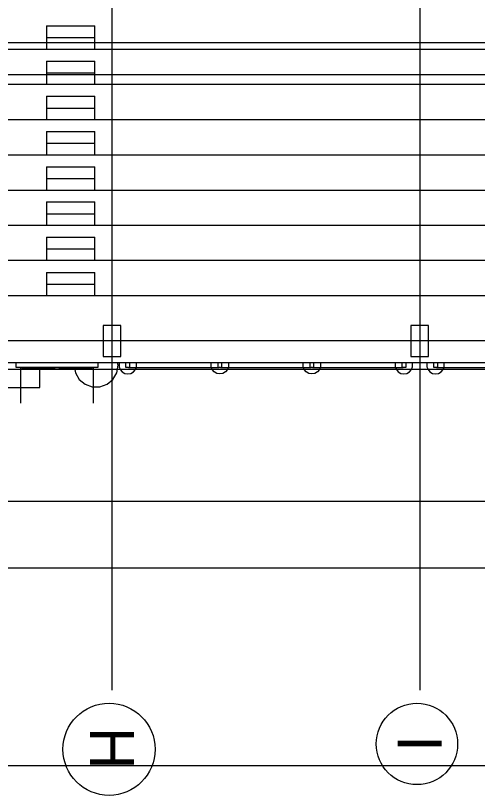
# Model space of a CAD drawing. Extents: x -264165 to -263575, y -1242333 to -1242036.
# Drawn here: x -263871.66 to -263861.16, y -1242251.13 to -1242233.41 of the extents above; entities that cross this region are included whole.
import ezdxf

# ---------------------------------------------------------------- set-up
doc = ezdxf.new("R2010")
doc.units = 0
doc.layers.add('KFA_HESCON_OSI_STAVBY', color=7, linetype='Continuous')
doc.layers.add('KFA_SITUACIA_DRS_VYTYCOVAK_SEDA', color=7, linetype='Continuous')

msp = doc.modelspace()

# ---------------------------------------------------------------- linework, layer by layer
at = {"layer": 'KFA_HESCON_OSI_STAVBY'}
for p, q in [((-263869.468, -1242080.447), (-263869.468, -1242248.737)), ((-263862.468, -1242080.447), (-263862.468, -1242248.737)), ((-263787.486, -1242234.032), (-263921.823, -1242234.032)), ((-263787.486, -1242240.807), (-263921.823, -1242240.807))]:
    msp.add_line(p, q, dxfattribs=at)
for centre, radius in [((-263869.533, -1242250.084), 1.047), ((-263862.533, -1242249.962), 0.925)]:
    msp.add_circle(centre, radius, dxfattribs=at)
at = {"layer": 'KFA_SITUACIA_DRS_VYTYCOVAK_SEDA'}
for p, q in [((-263870.956, -1242233.649), (-263870.956, -1242233.916)), ((-263870.956, -1242233.649), (-263870.956, -1242233.916)), ((-263870.956, -1242233.649), (-263869.856, -1242233.649)), ((-263870.956, -1242233.649), (-263869.856, -1242233.649)), ((-263869.856, -1242233.916), (-263869.856, -1242233.649)), ((-263869.856, -1242233.916), (-263869.856, -1242233.649)), ((-263870.956, -1242233.916), (-263869.856, -1242233.916)), ((-263870.956, -1242233.916), (-263869.856, -1242233.916)), ((-263870.956, -1242233.916), (-263870.956, -1242234.182)), ((-263870.956, -1242233.916), (-263870.956, -1242234.182)), ((-263869.856, -1242234.182), (-263869.856, -1242233.916)), ((-263869.856, -1242234.182), (-263869.856, -1242233.916)), ((-263869.468, -1242234.182), (-263876.468, -1242234.182)), ((-263869.468, -1242234.182), (-263876.468, -1242234.182)), ((-263862.468, -1242234.182), (-263869.468, -1242234.182)), ((-263862.468, -1242234.182), (-263869.468, -1242234.182)), ((-263855.468, -1242234.182), (-263862.468, -1242234.182)), ((-263855.468, -1242234.182), (-263862.468, -1242234.182)), ((-263870.956, -1242234.449), (-263870.956, -1242234.716)), ((-263870.956, -1242234.449), (-263870.956, -1242234.716)), ((-263870.956, -1242234.449), (-263869.856, -1242234.449)), ((-263870.956, -1242234.449), (-263869.856, -1242234.449)), ((-263869.856, -1242234.716), (-263869.856, -1242234.449)), ((-263869.856, -1242234.716), (-263869.856, -1242234.449)), ((-263812.068, -1242234.757), (-263891.868, -1242234.757)), ((-263870.956, -1242234.716), (-263869.856, -1242234.716)), ((-263870.956, -1242234.716), (-263869.856, -1242234.716)), ((-263870.956, -1242234.716), (-263870.956, -1242234.982)), ((-263870.956, -1242234.716), (-263870.956, -1242234.982)), ((-263869.856, -1242234.982), (-263869.856, -1242234.716)), ((-263869.856, -1242234.982), (-263869.856, -1242234.716)), ((-263869.468, -1242234.982), (-263876.468, -1242234.982)), ((-263869.468, -1242234.982), (-263876.468, -1242234.982)), ((-263862.468, -1242234.982), (-263869.468, -1242234.982)), ((-263862.468, -1242234.982), (-263869.468, -1242234.982)), ((-263855.468, -1242234.982), (-263862.468, -1242234.982)), ((-263855.468, -1242234.982), (-263862.468, -1242234.982)), ((-263870.956, -1242235.249), (-263870.956, -1242235.516)), ((-263870.956, -1242235.249), (-263870.956, -1242235.516)), ((-263870.956, -1242235.249), (-263869.856, -1242235.249)), ((-263870.956, -1242235.249), (-263869.856, -1242235.249)), ((-263869.856, -1242235.516), (-263869.856, -1242235.249)), ((-263869.856, -1242235.516), (-263869.856, -1242235.249)), ((-263870.956, -1242235.516), (-263869.856, -1242235.516)), ((-263870.956, -1242235.516), (-263869.856, -1242235.516)), ((-263870.956, -1242235.516), (-263870.956, -1242235.782)), ((-263870.956, -1242235.516), (-263870.956, -1242235.782)), ((-263869.856, -1242235.782), (-263869.856, -1242235.516)), ((-263869.856, -1242235.782), (-263869.856, -1242235.516)), ((-263869.468, -1242235.782), (-263876.468, -1242235.782)), ((-263869.468, -1242235.782), (-263876.468, -1242235.782)), ((-263862.468, -1242235.782), (-263869.468, -1242235.782)), ((-263862.468, -1242235.782), (-263869.468, -1242235.782)), ((-263855.468, -1242235.782), (-263862.468, -1242235.782)), ((-263855.468, -1242235.782), (-263862.468, -1242235.782)), ((-263870.956, -1242236.049), (-263870.956, -1242236.316)), ((-263870.956, -1242236.049), (-263870.956, -1242236.316)), ((-263870.956, -1242236.049), (-263869.856, -1242236.049)), ((-263870.956, -1242236.049), (-263869.856, -1242236.049)), ((-263869.856, -1242236.316), (-263869.856, -1242236.049)), ((-263869.856, -1242236.316), (-263869.856, -1242236.049)), ((-263870.956, -1242236.316), (-263869.856, -1242236.316)), ((-263870.956, -1242236.316), (-263869.856, -1242236.316)), ((-263870.956, -1242236.316), (-263870.956, -1242236.582)), ((-263870.956, -1242236.316), (-263870.956, -1242236.582)), ((-263869.856, -1242236.582), (-263869.856, -1242236.316)), ((-263869.856, -1242236.582), (-263869.856, -1242236.316)), ((-263869.468, -1242236.582), (-263876.468, -1242236.582)), ((-263869.468, -1242236.582), (-263876.468, -1242236.582)), ((-263862.468, -1242236.582), (-263869.468, -1242236.582)), ((-263862.468, -1242236.582), (-263869.468, -1242236.582)), ((-263855.468, -1242236.582), (-263862.468, -1242236.582)), ((-263855.468, -1242236.582), (-263862.468, -1242236.582)), ((-263870.956, -1242236.849), (-263870.956, -1242237.116)), ((-263870.956, -1242236.849), (-263870.956, -1242237.116)), ((-263870.956, -1242236.849), (-263869.856, -1242236.849)), ((-263870.956, -1242236.849), (-263869.856, -1242236.849)), ((-263869.856, -1242237.116), (-263869.856, -1242236.849)), ((-263869.856, -1242237.116), (-263869.856, -1242236.849)), ((-263870.956, -1242237.116), (-263869.856, -1242237.116)), ((-263870.956, -1242237.116), (-263869.856, -1242237.116)), ((-263870.956, -1242237.116), (-263870.956, -1242237.382)), ((-263870.956, -1242237.116), (-263870.956, -1242237.382)), ((-263869.856, -1242237.382), (-263869.856, -1242237.116)), ((-263869.856, -1242237.382), (-263869.856, -1242237.116)), ((-263876.468, -1242237.382), (-263869.468, -1242237.382)), ((-263876.468, -1242237.382), (-263869.468, -1242237.382)), ((-263869.468, -1242237.382), (-263862.468, -1242237.382)), ((-263869.468, -1242237.382), (-263862.468, -1242237.382)), ((-263862.468, -1242237.382), (-263855.468, -1242237.382)), ((-263862.468, -1242237.382), (-263855.468, -1242237.382)), ((-263870.956, -1242237.649), (-263870.956, -1242237.916)), ((-263870.956, -1242237.649), (-263870.956, -1242237.916)), ((-263870.956, -1242237.649), (-263869.856, -1242237.649)), ((-263870.956, -1242237.649), (-263869.856, -1242237.649)), ((-263869.856, -1242237.916), (-263869.856, -1242237.649)), ((-263869.856, -1242237.916), (-263869.856, -1242237.649)), ((-263870.956, -1242237.916), (-263869.856, -1242237.916)), ((-263870.956, -1242237.916), (-263869.856, -1242237.916)), ((-263870.956, -1242237.916), (-263870.956, -1242238.182)), ((-263870.956, -1242237.916), (-263870.956, -1242238.182)), ((-263869.856, -1242238.182), (-263869.856, -1242237.916)), ((-263869.856, -1242238.182), (-263869.856, -1242237.916)), ((-263869.468, -1242238.182), (-263876.468, -1242238.182)), ((-263869.468, -1242238.182), (-263876.468, -1242238.182)), ((-263862.468, -1242238.182), (-263869.468, -1242238.182)), ((-263862.468, -1242238.182), (-263869.468, -1242238.182)), ((-263855.468, -1242238.182), (-263862.468, -1242238.182)), ((-263855.468, -1242238.182), (-263862.468, -1242238.182)), ((-263870.956, -1242238.449), (-263870.956, -1242238.716)), ((-263870.956, -1242238.449), (-263870.956, -1242238.716)), ((-263870.956, -1242238.449), (-263869.856, -1242238.449)), ((-263870.956, -1242238.449), (-263869.856, -1242238.449)), ((-263869.856, -1242238.716), (-263869.856, -1242238.449)), ((-263869.856, -1242238.716), (-263869.856, -1242238.449)), ((-263870.956, -1242238.716), (-263869.856, -1242238.716)), ((-263870.956, -1242238.716), (-263869.856, -1242238.716)), ((-263870.956, -1242238.716), (-263870.956, -1242238.982)), ((-263870.956, -1242238.716), (-263870.956, -1242238.982)), ((-263869.856, -1242238.982), (-263869.856, -1242238.716)), ((-263869.856, -1242238.982), (-263869.856, -1242238.716)), ((-263869.468, -1242238.982), (-263876.468, -1242238.982)), ((-263869.468, -1242238.982), (-263876.468, -1242238.982)), ((-263862.468, -1242238.982), (-263869.468, -1242238.982)), ((-263862.468, -1242238.982), (-263869.468, -1242238.982)), ((-263855.468, -1242238.982), (-263862.468, -1242238.982)), ((-263855.468, -1242238.982), (-263862.468, -1242238.982)), ((-263870.956, -1242239.249), (-263870.956, -1242239.516)), ((-263870.956, -1242239.249), (-263870.956, -1242239.516)), ((-263870.956, -1242239.249), (-263869.856, -1242239.249)), ((-263870.956, -1242239.249), (-263869.856, -1242239.249)), ((-263869.856, -1242239.516), (-263869.856, -1242239.249)), ((-263869.856, -1242239.516), (-263869.856, -1242239.249)), ((-263870.956, -1242239.516), (-263869.856, -1242239.516)), ((-263870.956, -1242239.516), (-263869.856, -1242239.516)), ((-263870.956, -1242239.516), (-263870.956, -1242239.782)), ((-263870.956, -1242239.516), (-263870.956, -1242239.782)), ((-263869.856, -1242239.782), (-263869.856, -1242239.516)), ((-263869.856, -1242239.782), (-263869.856, -1242239.516)), ((-263869.468, -1242239.782), (-263876.468, -1242239.782)), ((-263869.468, -1242239.782), (-263876.468, -1242239.782)), ((-263862.468, -1242239.782), (-263869.468, -1242239.782)), ((-263862.468, -1242239.782), (-263869.468, -1242239.782)), ((-263855.468, -1242239.782), (-263862.468, -1242239.782)), ((-263855.468, -1242239.782), (-263862.468, -1242239.782)), ((-263869.668, -1242240.457), (-263869.668, -1242241.157)), ((-263869.668, -1242240.457), (-263869.668, -1242241.157)), ((-263869.468, -1242240.457), (-263869.668, -1242240.457)), ((-263869.468, -1242240.457), (-263869.668, -1242240.457)), ((-263869.268, -1242240.457), (-263869.468, -1242240.457)), ((-263869.268, -1242240.457), (-263869.468, -1242240.457)), ((-263869.268, -1242241.157), (-263869.268, -1242240.457)), ((-263869.268, -1242241.157), (-263869.268, -1242240.457)), ((-263862.668, -1242240.457), (-263862.668, -1242241.157)), ((-263862.668, -1242240.457), (-263862.668, -1242241.157)), ((-263862.468, -1242240.457), (-263862.668, -1242240.457)), ((-263862.468, -1242240.457), (-263862.668, -1242240.457)), ((-263862.268, -1242240.457), (-263862.468, -1242240.457)), ((-263862.268, -1242240.457), (-263862.468, -1242240.457)), ((-263862.268, -1242241.157), (-263862.268, -1242240.457)), ((-263862.268, -1242241.157), (-263862.268, -1242240.457)), ((-263869.668, -1242241.157), (-263869.468, -1242241.157)), ((-263869.668, -1242241.157), (-263869.468, -1242241.157)), ((-263869.468, -1242241.157), (-263869.268, -1242241.157)), ((-263869.468, -1242241.157), (-263869.268, -1242241.157)), ((-263862.668, -1242241.157), (-263862.468, -1242241.157)), ((-263862.668, -1242241.157), (-263862.468, -1242241.157)), ((-263862.468, -1242241.157), (-263862.268, -1242241.157)), ((-263862.468, -1242241.157), (-263862.268, -1242241.157)), ((-263869.468, -1242241.307), (-263876.468, -1242241.307)), ((-263869.468, -1242241.307), (-263876.468, -1242241.307)), ((-263869.478, -1242241.307), (-263876.458, -1242241.307)), ((-263869.478, -1242241.307), (-263876.458, -1242241.307)), ((-263871.648, -1242241.407), (-263871.648, -1242241.307)), ((-263871.648, -1242241.407), (-263871.648, -1242241.307)), ((-263869.788, -1242241.407), (-263871.648, -1242241.407)), ((-263869.788, -1242241.407), (-263871.648, -1242241.407)), ((-263871.543, -1242241.407), (-263871.543, -1242242.222)), ((-263871.543, -1242241.407), (-263871.543, -1242242.222)), ((-263871.543, -1242241.407), (-263871.517, -1242241.407)), ((-263871.543, -1242241.407), (-263871.517, -1242241.407)), ((-263871.517, -1242241.417), (-263871.517, -1242241.407)), ((-263871.517, -1242241.417), (-263871.517, -1242241.407)), ((-263870.758, -1242241.417), (-263870.758, -1242241.407)), ((-263870.758, -1242241.417), (-263870.758, -1242241.407)), ((-263870.758, -1242241.407), (-263870.728, -1242241.407)), ((-263870.758, -1242241.407), (-263870.728, -1242241.407)), ((-263870.758, -1242241.417), (-263870.758, -1242241.407)), ((-263870.758, -1242241.417), (-263870.758, -1242241.407)), ((-263870.708, -1242241.407), (-263870.677, -1242241.407)), ((-263870.708, -1242241.407), (-263870.677, -1242241.407)), ((-263870.678, -1242241.407), (-263870.678, -1242241.417)), ((-263870.678, -1242241.407), (-263870.678, -1242241.417)), ((-263870.677, -1242241.407), (-263870.677, -1242241.417)), ((-263870.677, -1242241.407), (-263870.677, -1242241.417)), ((-263869.918, -1242241.407), (-263869.893, -1242241.407)), ((-263869.918, -1242241.407), (-263869.893, -1242241.407)), ((-263869.918, -1242241.407), (-263869.918, -1242241.417)), ((-263869.918, -1242241.407), (-263869.918, -1242241.417)), ((-263869.893, -1242241.407), (-263869.893, -1242242.222)), ((-263869.893, -1242241.407), (-263869.893, -1242242.222)), ((-263869.788, -1242241.307), (-263869.788, -1242241.407)), ((-263869.788, -1242241.307), (-263869.788, -1242241.407)), ((-263869.458, -1242241.307), (-263869.478, -1242241.307)), ((-263869.458, -1242241.307), (-263869.478, -1242241.307)), ((-263862.468, -1242241.307), (-263869.468, -1242241.307)), ((-263862.468, -1242241.307), (-263869.468, -1242241.307)), ((-263862.478, -1242241.307), (-263869.458, -1242241.307)), ((-263862.478, -1242241.307), (-263869.458, -1242241.307)), ((-263869.358, -1242241.528), (-263869.328, -1242241.357)), ((-263869.358, -1242241.528), (-263869.328, -1242241.357)), ((-263869.328, -1242241.357), (-263869.337, -1242241.307)), ((-263869.328, -1242241.357), (-263869.337, -1242241.307)), ((-263869.299, -1242241.307), (-263869.305, -1242241.322)), ((-263869.299, -1242241.307), (-263869.305, -1242241.322)), ((-263869.305, -1242241.322), (-263869.305, -1242241.392)), ((-263869.305, -1242241.322), (-263869.305, -1242241.392)), ((-263869.305, -1242241.392), (-263869.281, -1242241.457)), ((-263869.305, -1242241.392), (-263869.281, -1242241.457)), ((-263869.148, -1242241.407), (-263869.148, -1242241.307)), ((-263869.148, -1242241.407), (-263869.148, -1242241.307)), ((-263869.091, -1242241.407), (-263869.148, -1242241.407)), ((-263869.091, -1242241.407), (-263869.148, -1242241.407)), ((-263869.091, -1242241.407), (-263869.091, -1242241.417)), ((-263869.091, -1242241.407), (-263869.091, -1242241.417)), ((-263869.068, -1242241.307), (-263869.068, -1242241.407)), ((-263869.068, -1242241.307), (-263869.068, -1242241.407)), ((-263869.068, -1242241.407), (-263867.054, -1242241.407)), ((-263869.068, -1242241.407), (-263867.054, -1242241.407)), ((-263868.911, -1242241.322), (-263868.916, -1242241.307)), ((-263868.911, -1242241.322), (-263868.916, -1242241.307)), ((-263868.916, -1242241.407), (-263868.911, -1242241.392)), ((-263868.916, -1242241.407), (-263868.911, -1242241.392)), ((-263868.911, -1242241.392), (-263868.911, -1242241.322)), ((-263868.911, -1242241.392), (-263868.911, -1242241.322)), ((-263867.211, -1242241.322), (-263867.206, -1242241.307)), ((-263867.211, -1242241.322), (-263867.206, -1242241.307)), ((-263867.211, -1242241.392), (-263867.211, -1242241.322)), ((-263867.211, -1242241.392), (-263867.211, -1242241.322)), ((-263867.206, -1242241.407), (-263867.211, -1242241.392)), ((-263867.206, -1242241.407), (-263867.211, -1242241.392)), ((-263867.054, -1242241.407), (-263867.054, -1242241.307)), ((-263867.054, -1242241.407), (-263867.054, -1242241.307)), ((-263867.032, -1242241.407), (-263867.032, -1242241.417)), ((-263867.032, -1242241.407), (-263867.032, -1242241.417)), ((-263866.997, -1242241.407), (-263867.032, -1242241.407)), ((-263866.997, -1242241.407), (-263867.032, -1242241.407)), ((-263866.997, -1242241.407), (-263866.997, -1242241.417)), ((-263866.997, -1242241.407), (-263866.997, -1242241.417)), ((-263866.974, -1242241.307), (-263866.974, -1242241.407)), ((-263866.974, -1242241.307), (-263866.974, -1242241.407)), ((-263866.974, -1242241.407), (-263864.961, -1242241.407)), ((-263866.974, -1242241.407), (-263864.961, -1242241.407)), ((-263866.823, -1242241.307), (-263866.818, -1242241.322)), ((-263866.823, -1242241.307), (-263866.818, -1242241.322)), ((-263866.818, -1242241.392), (-263866.823, -1242241.407)), ((-263866.818, -1242241.392), (-263866.823, -1242241.407)), ((-263866.818, -1242241.322), (-263866.818, -1242241.392)), ((-263866.818, -1242241.322), (-263866.818, -1242241.392)), ((-263865.118, -1242241.322), (-263865.113, -1242241.307)), ((-263865.118, -1242241.322), (-263865.113, -1242241.307)), ((-263865.118, -1242241.392), (-263865.118, -1242241.322)), ((-263865.118, -1242241.392), (-263865.118, -1242241.322)), ((-263865.113, -1242241.407), (-263865.118, -1242241.392)), ((-263865.113, -1242241.407), (-263865.118, -1242241.392)), ((-263864.961, -1242241.407), (-263864.961, -1242241.307)), ((-263864.961, -1242241.407), (-263864.961, -1242241.307)), ((-263864.938, -1242241.407), (-263864.938, -1242241.417)), ((-263864.938, -1242241.407), (-263864.938, -1242241.417)), ((-263864.904, -1242241.407), (-263864.938, -1242241.407)), ((-263864.904, -1242241.407), (-263864.938, -1242241.407)), ((-263864.904, -1242241.407), (-263864.904, -1242241.417)), ((-263864.904, -1242241.407), (-263864.904, -1242241.417)), ((-263864.881, -1242241.307), (-263864.881, -1242241.407)), ((-263864.881, -1242241.307), (-263864.881, -1242241.407)), ((-263864.881, -1242241.407), (-263862.845, -1242241.407)), ((-263864.881, -1242241.407), (-263862.845, -1242241.407)), ((-263864.73, -1242241.307), (-263864.724, -1242241.322)), ((-263864.73, -1242241.307), (-263864.724, -1242241.322)), ((-263864.724, -1242241.392), (-263864.73, -1242241.407)), ((-263864.724, -1242241.392), (-263864.73, -1242241.407)), ((-263864.724, -1242241.322), (-263864.724, -1242241.392)), ((-263864.724, -1242241.322), (-263864.724, -1242241.392)), ((-263863.019, -1242241.307), (-263863.025, -1242241.322)), ((-263863.019, -1242241.307), (-263863.025, -1242241.322)), ((-263863.025, -1242241.322), (-263863.025, -1242241.392)), ((-263863.025, -1242241.322), (-263863.025, -1242241.392)), ((-263863.025, -1242241.392), (-263863.019, -1242241.407)), ((-263863.025, -1242241.392), (-263863.019, -1242241.407)), ((-263862.868, -1242241.407), (-263862.868, -1242241.307)), ((-263862.868, -1242241.407), (-263862.868, -1242241.307)), ((-263862.788, -1242241.407), (-263862.868, -1242241.407)), ((-263862.788, -1242241.407), (-263862.868, -1242241.407)), ((-263862.845, -1242241.407), (-263862.845, -1242241.417)), ((-263862.845, -1242241.407), (-263862.845, -1242241.417)), ((-263862.788, -1242241.307), (-263862.788, -1242241.407)), ((-263862.788, -1242241.307), (-263862.788, -1242241.407)), ((-263862.655, -1242241.457), (-263862.631, -1242241.392)), ((-263862.655, -1242241.457), (-263862.631, -1242241.392)), ((-263862.631, -1242241.322), (-263862.636, -1242241.307)), ((-263862.631, -1242241.322), (-263862.636, -1242241.307)), ((-263862.631, -1242241.392), (-263862.631, -1242241.322)), ((-263862.631, -1242241.392), (-263862.631, -1242241.322)), ((-263862.458, -1242241.307), (-263862.478, -1242241.307)), ((-263862.458, -1242241.307), (-263862.478, -1242241.307)), ((-263855.468, -1242241.307), (-263862.468, -1242241.307)), ((-263855.468, -1242241.307), (-263862.468, -1242241.307)), ((-263855.478, -1242241.307), (-263862.458, -1242241.307)), ((-263855.478, -1242241.307), (-263862.458, -1242241.307)), ((-263862.299, -1242241.307), (-263862.305, -1242241.322)), ((-263862.299, -1242241.307), (-263862.305, -1242241.322)), ((-263862.305, -1242241.322), (-263862.305, -1242241.392)), ((-263862.305, -1242241.322), (-263862.305, -1242241.392)), ((-263862.305, -1242241.392), (-263862.281, -1242241.457)), ((-263862.305, -1242241.392), (-263862.281, -1242241.457)), ((-263862.148, -1242241.407), (-263862.148, -1242241.307)), ((-263862.148, -1242241.407), (-263862.148, -1242241.307)), ((-263862.068, -1242241.407), (-263862.148, -1242241.407)), ((-263862.068, -1242241.407), (-263862.148, -1242241.407)), ((-263862.091, -1242241.417), (-263862.091, -1242241.407)), ((-263862.091, -1242241.417), (-263862.091, -1242241.407)), ((-263862.091, -1242241.407), (-263860.054, -1242241.407)), ((-263862.091, -1242241.407), (-263860.054, -1242241.407)), ((-263862.068, -1242241.307), (-263862.068, -1242241.407)), ((-263862.068, -1242241.307), (-263862.068, -1242241.407)), ((-263861.911, -1242241.322), (-263861.916, -1242241.307)), ((-263861.911, -1242241.322), (-263861.916, -1242241.307)), ((-263861.916, -1242241.407), (-263861.911, -1242241.392)), ((-263861.916, -1242241.407), (-263861.911, -1242241.392)), ((-263861.911, -1242241.392), (-263861.911, -1242241.322)), ((-263861.911, -1242241.392), (-263861.911, -1242241.322)), ((-263808.968, -1242241.457), (-263894.968, -1242241.457)), ((-263871.517, -1242241.417), (-263870.758, -1242241.417)), ((-263871.517, -1242241.417), (-263870.758, -1242241.417)), ((-263871.108, -1242241.868), (-263871.108, -1242241.417)), ((-263871.108, -1242241.868), (-263871.108, -1242241.417)), ((-263870.678, -1242241.417), (-263870.758, -1242241.417)), ((-263870.678, -1242241.417), (-263870.758, -1242241.417)), ((-263870.677, -1242241.417), (-263869.918, -1242241.417)), ((-263870.677, -1242241.417), (-263869.918, -1242241.417)), ((-263870.317, -1242241.417), (-263870.298, -1242241.528)), ((-263870.317, -1242241.417), (-263870.298, -1242241.528)), ((-263870.298, -1242241.528), (-263870.211, -1242241.679)), ((-263870.298, -1242241.528), (-263870.211, -1242241.679)), ((-263869.445, -1242241.679), (-263869.358, -1242241.528)), ((-263869.445, -1242241.679), (-263869.358, -1242241.528)), ((-263869.281, -1242241.457), (-263869.236, -1242241.51)), ((-263869.281, -1242241.457), (-263869.236, -1242241.51)), ((-263869.236, -1242241.51), (-263869.176, -1242241.545)), ((-263869.236, -1242241.51), (-263869.176, -1242241.545)), ((-263869.176, -1242241.545), (-263869.108, -1242241.557)), ((-263869.176, -1242241.545), (-263869.108, -1242241.557)), ((-263869.108, -1242241.557), (-263869.039, -1242241.545)), ((-263869.108, -1242241.557), (-263869.039, -1242241.545)), ((-263867.032, -1242241.417), (-263869.091, -1242241.417)), ((-263867.032, -1242241.417), (-263869.091, -1242241.417)), ((-263869.039, -1242241.545), (-263868.979, -1242241.51)), ((-263869.039, -1242241.545), (-263868.979, -1242241.51)), ((-263868.979, -1242241.51), (-263868.935, -1242241.457)), ((-263868.979, -1242241.51), (-263868.935, -1242241.457)), ((-263868.935, -1242241.457), (-263868.92, -1242241.417)), ((-263868.935, -1242241.457), (-263868.92, -1242241.417)), ((-263867.188, -1242241.457), (-263867.202, -1242241.417)), ((-263867.188, -1242241.457), (-263867.202, -1242241.417)), ((-263867.143, -1242241.51), (-263867.188, -1242241.457)), ((-263867.143, -1242241.51), (-263867.188, -1242241.457)), ((-263867.083, -1242241.545), (-263867.143, -1242241.51)), ((-263867.083, -1242241.545), (-263867.143, -1242241.51)), ((-263867.014, -1242241.557), (-263867.083, -1242241.545)), ((-263867.014, -1242241.557), (-263867.083, -1242241.545)), ((-263866.946, -1242241.545), (-263867.014, -1242241.557)), ((-263866.946, -1242241.545), (-263867.014, -1242241.557)), ((-263864.938, -1242241.417), (-263866.997, -1242241.417)), ((-263864.938, -1242241.417), (-263866.997, -1242241.417)), ((-263866.886, -1242241.51), (-263866.946, -1242241.545)), ((-263866.886, -1242241.51), (-263866.946, -1242241.545)), ((-263866.841, -1242241.457), (-263866.886, -1242241.51)), ((-263866.841, -1242241.457), (-263866.886, -1242241.51)), ((-263866.827, -1242241.417), (-263866.841, -1242241.457)), ((-263866.827, -1242241.417), (-263866.841, -1242241.457)), ((-263865.094, -1242241.457), (-263865.109, -1242241.417)), ((-263865.094, -1242241.457), (-263865.109, -1242241.417)), ((-263865.05, -1242241.51), (-263865.094, -1242241.457)), ((-263865.05, -1242241.51), (-263865.094, -1242241.457)), ((-263864.99, -1242241.545), (-263865.05, -1242241.51)), ((-263864.99, -1242241.545), (-263865.05, -1242241.51)), ((-263864.921, -1242241.557), (-263864.99, -1242241.545)), ((-263864.921, -1242241.557), (-263864.99, -1242241.545)), ((-263864.853, -1242241.545), (-263864.921, -1242241.557)), ((-263864.853, -1242241.545), (-263864.921, -1242241.557)), ((-263862.845, -1242241.417), (-263864.904, -1242241.417)), ((-263862.845, -1242241.417), (-263864.904, -1242241.417)), ((-263864.793, -1242241.51), (-263864.853, -1242241.545)), ((-263864.793, -1242241.51), (-263864.853, -1242241.545)), ((-263864.748, -1242241.457), (-263864.793, -1242241.51)), ((-263864.748, -1242241.457), (-263864.793, -1242241.51)), ((-263864.733, -1242241.417), (-263864.748, -1242241.457)), ((-263864.733, -1242241.417), (-263864.748, -1242241.457)), ((-263863.016, -1242241.417), (-263863.001, -1242241.457)), ((-263863.016, -1242241.417), (-263863.001, -1242241.457)), ((-263863.001, -1242241.457), (-263862.956, -1242241.51)), ((-263863.001, -1242241.457), (-263862.956, -1242241.51)), ((-263862.956, -1242241.51), (-263862.896, -1242241.545)), ((-263862.956, -1242241.51), (-263862.896, -1242241.545)), ((-263862.896, -1242241.545), (-263862.828, -1242241.557)), ((-263862.896, -1242241.545), (-263862.828, -1242241.557)), ((-263862.828, -1242241.557), (-263862.759, -1242241.545)), ((-263862.828, -1242241.557), (-263862.759, -1242241.545)), ((-263862.759, -1242241.545), (-263862.699, -1242241.51)), ((-263862.759, -1242241.545), (-263862.699, -1242241.51)), ((-263862.699, -1242241.51), (-263862.655, -1242241.457)), ((-263862.699, -1242241.51), (-263862.655, -1242241.457)), ((-263862.281, -1242241.457), (-263862.236, -1242241.51)), ((-263862.281, -1242241.457), (-263862.236, -1242241.51)), ((-263862.236, -1242241.51), (-263862.176, -1242241.545)), ((-263862.236, -1242241.51), (-263862.176, -1242241.545)), ((-263862.176, -1242241.545), (-263862.108, -1242241.557)), ((-263862.176, -1242241.545), (-263862.108, -1242241.557)), ((-263862.108, -1242241.557), (-263862.039, -1242241.545)), ((-263862.108, -1242241.557), (-263862.039, -1242241.545)), ((-263860.032, -1242241.417), (-263862.091, -1242241.417)), ((-263860.032, -1242241.417), (-263862.091, -1242241.417)), ((-263862.039, -1242241.545), (-263861.979, -1242241.51)), ((-263862.039, -1242241.545), (-263861.979, -1242241.51)), ((-263861.979, -1242241.51), (-263861.935, -1242241.457)), ((-263861.979, -1242241.51), (-263861.935, -1242241.457)), ((-263861.935, -1242241.457), (-263861.92, -1242241.417)), ((-263861.935, -1242241.457), (-263861.92, -1242241.417)), ((-263870.211, -1242241.679), (-263870.078, -1242241.79)), ((-263870.211, -1242241.679), (-263870.078, -1242241.79)), ((-263869.578, -1242241.79), (-263869.445, -1242241.679)), ((-263869.578, -1242241.79), (-263869.445, -1242241.679)), ((-263874.828, -1242241.868), (-263871.108, -1242241.868)), ((-263874.828, -1242241.868), (-263871.108, -1242241.868)), ((-263870.078, -1242241.79), (-263869.915, -1242241.85)), ((-263870.078, -1242241.79), (-263869.915, -1242241.85)), ((-263869.915, -1242241.85), (-263869.741, -1242241.85)), ((-263869.915, -1242241.85), (-263869.741, -1242241.85)), ((-263869.741, -1242241.85), (-263869.578, -1242241.79)), ((-263869.741, -1242241.85), (-263869.578, -1242241.79)), ((-263851.968, -1242244.458), (-263896.21, -1242244.458)), ((-263896.71, -1242245.958), (-263808.225, -1242245.958)), ((-263807.725, -1242250.458), (-263917.593, -1242250.458))]:
    msp.add_line(p, q, dxfattribs=at)

# ---------------------------------------------------------------- texts
at = {"layer": 'KFA_HESCON_OSI_STAVBY'}
for s, p in [('H', (-263869.968, -1242249.58)), ('I', (-263862.968, -1242249.768))]:
    msp.add_text(s, height=1, rotation=270, dxfattribs=at).set_placement(p)

doc.saveas('drawing.dxf')
